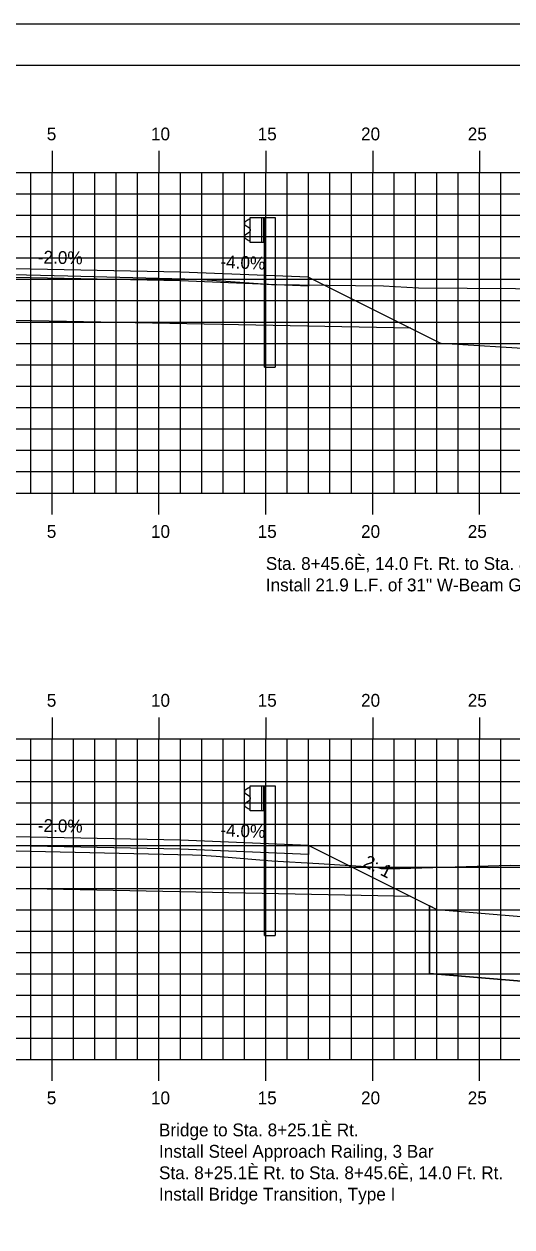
# Model space of a CAD drawing. Extents: x 2194256 to 2194747, y 863888 to 863998.
# Drawn here: x 2194480.4 to 2194503.3, y 863942.1 to 863998.4 of the extents above; entities that cross this region are included whole.
import ezdxf

# ---------------------------------------------------------------- set-up
doc = ezdxf.new("R2010")
doc.units = 0
for name, color, linetype in [('ANNOTATION', 7, 'Continuous'), ('BORDER', 7, 'Continuous'), ('D_Guardrail_Beam_Lt', 7, 'Continuous'), ('H_V ANNOTATION', 7, 'Continuous'), ('MAJOR', 7, 'Continuous'), ('MINOR', 7, 'Continuous'), ('Patterning', 7, 'Continuous'), ('PLOT BOUNDARY', 7, 'Continuous'), ('S_Roadway_Centerline', 7, 'Continuous'), ('TEMPLATE', 7, 'Continuous')]:
    doc.layers.add(name, color=color, linetype=linetype)

msp = doc.modelspace()

# ---------------------------------------------------------------- linework, layer by layer
at = {"layer": 'BORDER'}
msp.add_lwpolyline([(2194401.743, 863891.446), (2194561.743, 863891.446), (2194561.743, 863996.446), (2194401.743, 863996.446)], close=True, dxfattribs=at)
at = {"layer": 'D_Guardrail_Beam_Lt'}
for p, q in [((2194490.924, 863989.228), (2194490.78, 863989.128)), ((2194490.78, 863988.985), (2194490.976, 863988.849)), ((2194491.014, 863989.249), (2194490.939, 863989.235)), ((2194491.014, 863989.332), (2194491.701, 863989.332)), ((2194491.014, 863988.166), (2194491.014, 863989.332)), ((2194491.534, 863989.332), (2194491.534, 863988.166)), ((2194491.639, 863989.332), (2194491.639, 863988.166)), ((2194491.701, 863989.332), (2194492.172, 863989.332)), ((2194491.701, 863989.332), (2194491.701, 863988.166)), ((2194492.172, 863989.332), (2194492.172, 863982.332)), ((2194490.976, 863988.65), (2194490.78, 863988.513)), ((2194490.78, 863988.37), (2194490.924, 863988.27)), ((2194491.009, 863988.784), (2194491.009, 863988.714)), ((2194490.939, 863988.264), (2194491.014, 863988.249)), ((2194491.701, 863988.166), (2194491.014, 863988.166)), ((2194491.68, 863982.332), (2194491.68, 863988.166)), ((2194491.68, 863982.332), (2194492.172, 863982.332)), ((2194490.924, 863962.638), (2194490.78, 863962.538)), ((2194491.014, 863962.659), (2194490.939, 863962.645)), ((2194491.014, 863962.742), (2194491.701, 863962.742)), ((2194491.014, 863961.576), (2194491.014, 863962.742)), ((2194491.534, 863962.742), (2194491.534, 863961.576)), ((2194491.639, 863962.742), (2194491.639, 863961.576)), ((2194491.701, 863962.742), (2194492.172, 863962.742)), ((2194491.701, 863962.742), (2194491.701, 863961.576)), ((2194492.172, 863962.742), (2194492.172, 863955.742)), ((2194490.78, 863962.395), (2194490.976, 863962.259)), ((2194490.976, 863962.06), (2194490.78, 863961.923)), ((2194491.009, 863962.194), (2194491.009, 863962.124)), ((2194490.78, 863961.78), (2194490.924, 863961.68)), ((2194490.939, 863961.674), (2194491.014, 863961.659)), ((2194491.701, 863961.576), (2194491.014, 863961.576)), ((2194491.68, 863955.742), (2194491.68, 863961.576)), ((2194491.68, 863955.742), (2194492.172, 863955.742))]:
    msp.add_line(p, q, dxfattribs=at)
for centre, major_axis, start_param, end_param in [((2194490.83, 863989.056), (-0.0877, 0), 5.323254, 7.243116), ((2194490.948, 863989.194), (-0.0417, 0), 4.907132, 5.323254), ((2194490.83, 863988.442), (-0.0877, 0), 5.323254, 7.243116), ((2194490.93, 863988.784), (0.0789, 0), 0, 0.959931), ((2194490.93, 863988.714), (0.0789, 0), 5.323254, 6.283185), ((2194490.948, 863988.304), (-0.0417, 0), 0.959931, 1.376053), ((2194490.83, 863962.466), (-0.0877, 0), 5.323254, 7.243116), ((2194490.948, 863962.604), (-0.0417, 0), 4.907132, 5.323254), ((2194490.83, 863961.852), (-0.0877, 0), 5.323254, 7.243116), ((2194490.93, 863962.194), (0.0789, 0), 0, 0.959931), ((2194490.93, 863962.124), (0.0789, 0), 5.323254, 6.283185), ((2194490.948, 863961.714), (-0.0417, 0), 0.959931, 1.376053)]:
    msp.add_ellipse(centre, major_axis=major_axis, ratio=0.995501, start_param=start_param, end_param=end_param, dxfattribs=at)
at = {"layer": 'MAJOR'}
for p, q in [((2194481.743, 863992.448), (2194481.743, 863991.446)), ((2194486.743, 863992.448), (2194486.743, 863991.446)), ((2194491.743, 863992.448), (2194491.743, 863991.446)), ((2194496.743, 863992.448), (2194496.743, 863991.446)), ((2194501.743, 863992.448), (2194501.743, 863991.446)), ((2194406.743, 863991.446), (2194546.743, 863991.446)), ((2194481.743, 863976.446), (2194481.743, 863991.446)), ((2194486.743, 863976.446), (2194486.743, 863991.446)), ((2194491.743, 863976.446), (2194491.743, 863991.446)), ((2194496.743, 863976.446), (2194496.743, 863991.446)), ((2194501.743, 863976.446), (2194501.743, 863991.446)), ((2194406.743, 863986.446), (2194546.743, 863986.446)), ((2194406.743, 863981.446), (2194546.743, 863981.446)), ((2194406.743, 863976.446), (2194546.743, 863976.446)), ((2194481.743, 863975.444), (2194481.743, 863976.446)), ((2194486.743, 863975.444), (2194486.743, 863976.446)), ((2194491.743, 863975.444), (2194491.743, 863976.446)), ((2194496.743, 863975.444), (2194496.743, 863976.446)), ((2194501.743, 863975.444), (2194501.743, 863976.446)), ((2194481.743, 863965.948), (2194481.743, 863964.946)), ((2194486.743, 863965.948), (2194486.743, 863964.946)), ((2194491.743, 863965.948), (2194491.743, 863964.946)), ((2194496.743, 863965.948), (2194496.743, 863964.946)), ((2194501.743, 863965.948), (2194501.743, 863964.946)), ((2194406.743, 863964.946), (2194546.743, 863964.946)), ((2194406.743, 863964.946), (2194546.743, 863964.946)), ((2194481.743, 863949.946), (2194481.743, 863964.946)), ((2194486.743, 863949.946), (2194486.743, 863964.946)), ((2194491.743, 863949.946), (2194491.743, 863964.946)), ((2194496.743, 863949.946), (2194496.743, 863964.946)), ((2194501.743, 863949.946), (2194501.743, 863964.946)), ((2194406.743, 863959.946), (2194546.743, 863959.946)), ((2194406.743, 863954.946), (2194546.743, 863954.946)), ((2194406.743, 863949.946), (2194546.743, 863949.946)), ((2194481.743, 863948.944), (2194481.743, 863949.946)), ((2194486.743, 863948.944), (2194486.743, 863949.946)), ((2194491.743, 863948.944), (2194491.743, 863949.946)), ((2194496.743, 863948.944), (2194496.743, 863949.946)), ((2194501.743, 863948.944), (2194501.743, 863949.946))]:
    msp.add_line(p, q, dxfattribs=at)
at = {"layer": 'MINOR'}
for p, q in [((2194480.743, 863976.446), (2194480.743, 863991.446)), ((2194482.743, 863976.446), (2194482.743, 863991.446)), ((2194483.743, 863976.446), (2194483.743, 863991.446)), ((2194484.743, 863976.446), (2194484.743, 863991.446)), ((2194485.743, 863976.446), (2194485.743, 863991.446)), ((2194487.743, 863976.446), (2194487.743, 863991.446)), ((2194488.743, 863976.446), (2194488.743, 863991.446)), ((2194489.743, 863976.446), (2194489.743, 863991.446)), ((2194490.743, 863976.446), (2194490.743, 863991.446)), ((2194492.743, 863976.446), (2194492.743, 863991.446)), ((2194493.743, 863976.446), (2194493.743, 863991.446)), ((2194494.743, 863976.446), (2194494.743, 863991.446)), ((2194495.743, 863976.446), (2194495.743, 863991.446)), ((2194497.743, 863976.446), (2194497.743, 863991.446)), ((2194498.743, 863976.446), (2194498.743, 863991.446)), ((2194499.743, 863976.446), (2194499.743, 863991.446)), ((2194500.743, 863976.446), (2194500.743, 863991.446)), ((2194502.743, 863976.446), (2194502.743, 863991.446)), ((2194406.743, 863990.446), (2194546.743, 863990.446)), ((2194406.743, 863989.446), (2194546.743, 863989.446)), ((2194406.743, 863988.446), (2194546.743, 863988.446)), ((2194406.743, 863987.446), (2194546.743, 863987.446)), ((2194406.743, 863985.446), (2194546.743, 863985.446)), ((2194406.743, 863984.446), (2194546.743, 863984.446)), ((2194406.743, 863983.446), (2194546.743, 863983.446)), ((2194406.743, 863982.446), (2194546.743, 863982.446)), ((2194406.743, 863980.446), (2194546.743, 863980.446)), ((2194406.743, 863979.446), (2194546.743, 863979.446)), ((2194406.743, 863978.446), (2194546.743, 863978.446)), ((2194406.743, 863977.446), (2194546.743, 863977.446)), ((2194480.743, 863949.946), (2194480.743, 863964.946)), ((2194482.743, 863949.946), (2194482.743, 863964.946)), ((2194483.743, 863949.946), (2194483.743, 863964.946)), ((2194484.743, 863949.946), (2194484.743, 863964.946)), ((2194485.743, 863949.946), (2194485.743, 863964.946)), ((2194487.743, 863949.946), (2194487.743, 863964.946)), ((2194488.743, 863949.946), (2194488.743, 863964.946)), ((2194489.743, 863949.946), (2194489.743, 863964.946)), ((2194490.743, 863949.946), (2194490.743, 863964.946)), ((2194492.743, 863949.946), (2194492.743, 863964.946)), ((2194493.743, 863949.946), (2194493.743, 863964.946)), ((2194494.743, 863949.946), (2194494.743, 863964.946)), ((2194495.743, 863949.946), (2194495.743, 863964.946)), ((2194497.743, 863949.946), (2194497.743, 863964.946)), ((2194498.743, 863949.946), (2194498.743, 863964.946)), ((2194499.743, 863949.946), (2194499.743, 863964.946)), ((2194500.743, 863949.946), (2194500.743, 863964.946)), ((2194502.743, 863949.946), (2194502.743, 863964.946)), ((2194406.743, 863963.946), (2194546.743, 863963.946)), ((2194406.743, 863962.946), (2194546.743, 863962.946)), ((2194406.743, 863961.946), (2194546.743, 863961.946)), ((2194406.743, 863960.946), (2194546.743, 863960.946)), ((2194406.743, 863958.946), (2194546.743, 863958.946)), ((2194406.743, 863957.946), (2194546.743, 863957.946)), ((2194406.743, 863956.946), (2194546.743, 863956.946)), ((2194406.743, 863955.946), (2194546.743, 863955.946)), ((2194406.743, 863953.946), (2194546.743, 863953.946)), ((2194406.743, 863952.946), (2194546.743, 863952.946)), ((2194406.743, 863951.946), (2194546.743, 863951.946)), ((2194406.743, 863950.946), (2194546.743, 863950.946))]:
    msp.add_line(p, q, dxfattribs=at)
at = {"layer": 'Patterning'}
msp.add_line((2194499.4, 863957.127), (2194499.4, 863953.966), dxfattribs=at)
for points in [[(2194536.545, 863951.946), (2194533.328, 863952.946), (2194526.106, 863953.946), (2194518.899, 863954.946), (2194511.723, 863955.946), (2194499.763, 863956.946), (2194499.4, 863957.127)], [(2194499.4, 863953.966), (2194511.39, 863952.963), (2194518.486, 863951.974), (2194525.694, 863950.974), (2194532.672, 863950.008), (2194533.744, 863949.675)]]:
    msp.add_lwpolyline(points, dxfattribs=at)
at = {"layer": 'PLOT BOUNDARY'}
msp.add_lwpolyline([(2194393.65, 863888.387), (2194563.65, 863888.387), (2194563.65, 863998.387), (2194393.65, 863998.387)], close=True, dxfattribs=at)
at = {"layer": 'S_Roadway_Centerline'}
msp.add_line((2194499.4, 863953.966), (2194499.4, 863957.127), dxfattribs=at)
for points in [[(2194406.743, 863984.776), (2194413.814, 863984.462), (2194422.331, 863983.975), (2194424.939, 863983.173), (2194440.092, 863981.136), (2194445.1, 863982.351), (2194450.863, 863983.373), (2194461.063, 863986.367), (2194463.856, 863986.522), (2194465.566, 863986.66), (2194471.54, 863986.672), (2194476.678, 863986.745), (2194482.483, 863986.609), (2194488.569, 863986.453), (2194490.962, 863986.285), (2194492.004, 863986.208), (2194497.241, 863986.134), (2194498.885, 863986.051), (2194505.695, 863985.992)], [(2194436.828, 863955.919), (2194441.916, 863955.643), (2194450.241, 863956.094), (2194459.622, 863958.832), (2194461.531, 863959.171), (2194462.152, 863959.353), (2194462.322, 863959.362), (2194465.731, 863959.637), (2194466.254, 863959.638), (2194476.612, 863959.784), (2194488.315, 863959.51), (2194488.716, 863959.5), (2194489.419, 863959.45), (2194492.028, 863959.243), (2194494.216, 863959.118), (2194496.931, 863958.932), (2194497.146, 863958.884), (2194498.014, 863958.878), (2194503.173, 863959.04), (2194509.394, 863958.986)], [(2194533.744, 863949.675), (2194532.672, 863950.008), (2194525.694, 863950.974), (2194518.486, 863951.974), (2194511.39, 863952.963), (2194499.4, 863953.966)]]:
    msp.add_lwpolyline(points, dxfattribs=at)
at = {"layer": 'TEMPLATE'}
for p, q in [((2194487.743, 863986.786), (2194476.743, 863987.006)), ((2194493.743, 863986.546), (2194487.743, 863986.786)), ((2194487.743, 863986.369), (2194476.743, 863986.589)), ((2194493.743, 863986.546), (2194499.943, 863983.446)), ((2194498.527, 863984.153), (2194476.743, 863984.589)), ((2194515.866, 863982.446), (2194499.943, 863983.446)), ((2194487.743, 863960.196), (2194476.743, 863960.416)), ((2194493.743, 863959.956), (2194487.743, 863960.196)), ((2194487.743, 863959.779), (2194476.743, 863959.999)), ((2194498.527, 863957.563), (2194476.743, 863957.999))]:
    msp.add_line(p, q, dxfattribs=at)
for points in [[(2194493.743, 863986.546), (2194493.743, 863986.129), (2194487.743, 863986.369)], [(2194493.743, 863959.956), (2194493.743, 863959.539), (2194487.743, 863959.779)], [(2194536.545, 863951.946), (2194533.328, 863952.946), (2194526.106, 863953.946), (2194518.899, 863954.946), (2194511.723, 863955.946), (2194499.763, 863956.946), (2194493.743, 863959.956)]]:
    msp.add_lwpolyline(points, dxfattribs=at)

# ---------------------------------------------------------------- texts
at = {"layer": 'ANNOTATION'}
for s, rotation, p in [('-2.0%', 358.8542, (2194481.071, 863987.186)), ('-4.0%', 357.7094, (2194489.609, 863986.978)), ('-2.0%', 358.8542, (2194481.071, 863960.596)), ('-4.0%', 357.7094, (2194489.609, 863960.388)), ('2: 1', 333.4349, (2194496.256, 863958.998))]:
    msp.add_text(s, height=0.6, rotation=rotation, dxfattribs=at).set_placement(p)
for s, p in [('Sta. 8+45.6È, 14.0 Ft. Rt. to Sta. 8+67.5È, 14.0 Ft. Rt.', (2194491.743, 863972.846)), ('Install 21.9 L.F. of 31" W-Beam Guardrail', (2194491.743, 863971.844)), ('Bridge to Sta. 8+25.1È Rt.', (2194486.743, 863946.346)), ('Install Steel Approach Railing, 3 Bar', (2194486.743, 863945.344)), ('Sta. 8+25.1È Rt. to Sta. 8+45.6È, 14.0 Ft. Rt.', (2194486.743, 863944.342)), ('Install Bridge Transition, Type I', (2194486.743, 863943.34))]:
    msp.add_text(s, height=0.6, dxfattribs=at).set_placement(p)
at = {"layer": 'H_V ANNOTATION'}
for s, p in [('5', (2194481.494, 863992.946)), ('10', (2194486.368, 863992.946)), ('15', (2194491.36, 863992.946)), ('20', (2194496.197, 863992.946)), ('25', (2194501.189, 863992.946)), ('5', (2194481.494, 863974.346)), ('10', (2194486.368, 863974.346)), ('15', (2194491.36, 863974.346)), ('20', (2194496.197, 863974.346)), ('25', (2194501.189, 863974.346)), ('5', (2194481.494, 863966.446)), ('10', (2194486.368, 863966.446)), ('15', (2194491.36, 863966.446)), ('20', (2194496.197, 863966.446)), ('25', (2194501.189, 863966.446)), ('5', (2194481.494, 863947.846)), ('10', (2194486.368, 863947.846)), ('15', (2194491.36, 863947.846)), ('20', (2194496.197, 863947.846)), ('25', (2194501.189, 863947.846))]:
    msp.add_text(s, height=0.6, dxfattribs=at).set_placement(p)

doc.saveas('drawing.dxf')
